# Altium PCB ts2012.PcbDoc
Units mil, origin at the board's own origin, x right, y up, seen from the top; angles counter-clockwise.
Board outline 1935.03 x 1190.03 mil, 2 copper layers (Top Layer, Bottom Layer); 16 components, 15 nets, 62 pads, 7 vias.
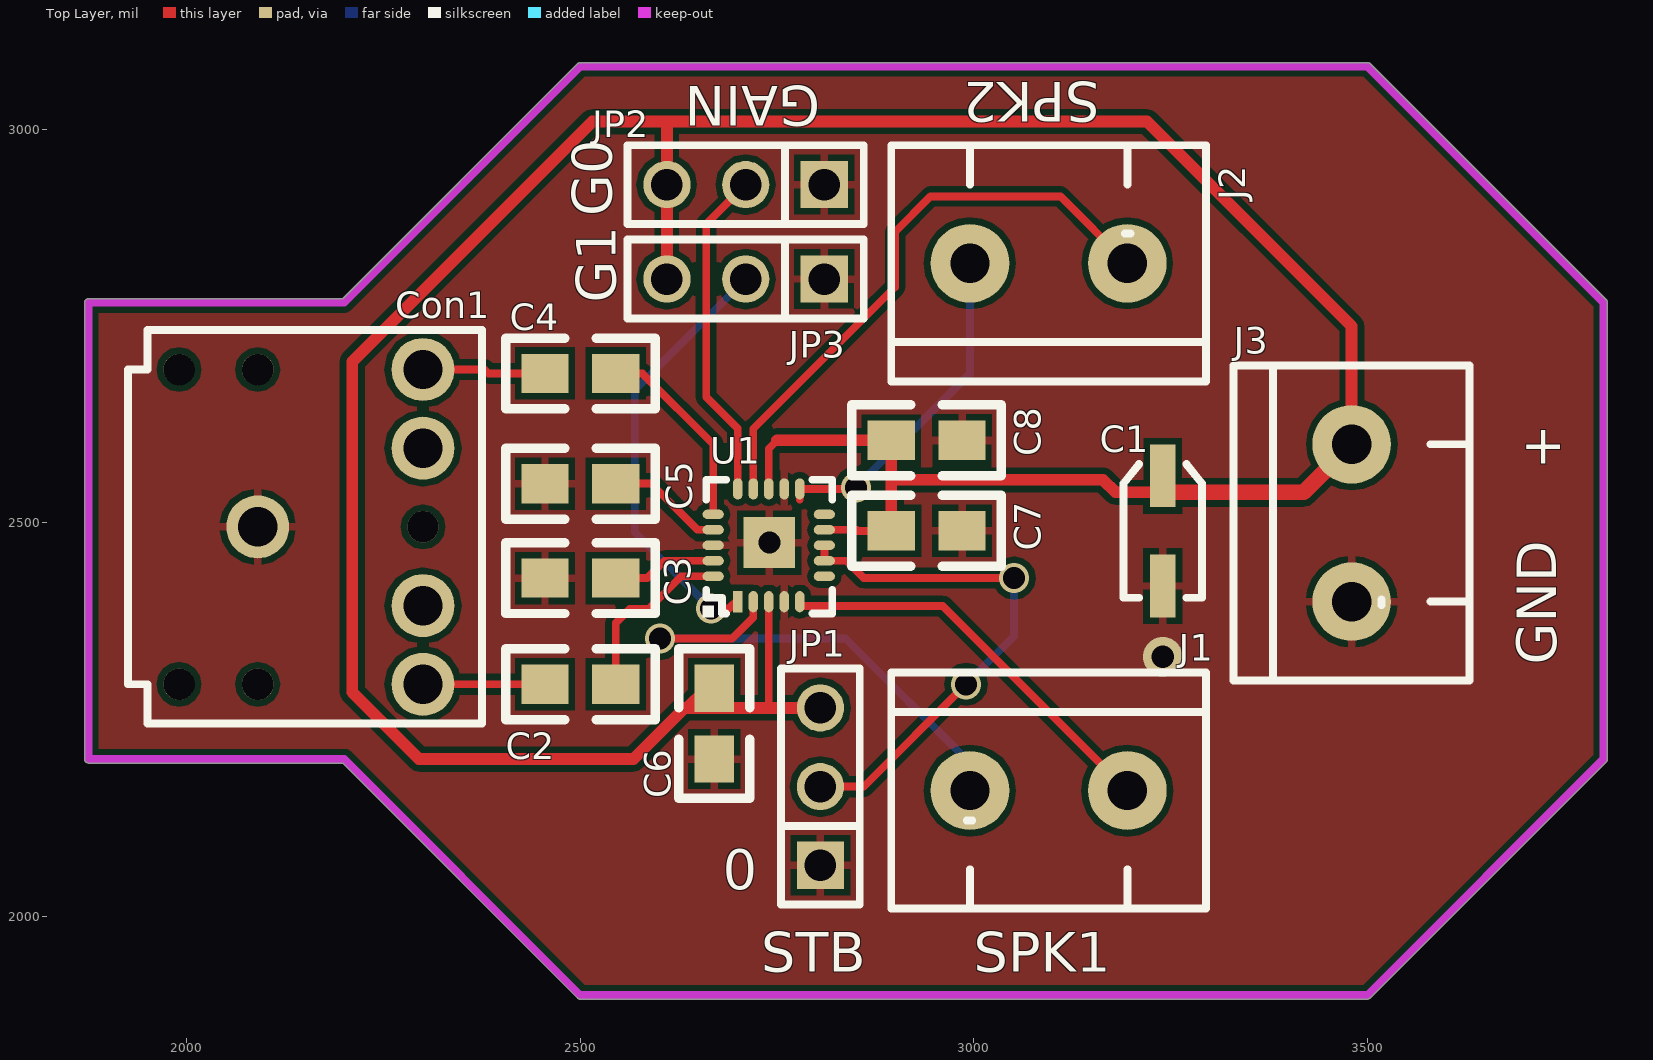
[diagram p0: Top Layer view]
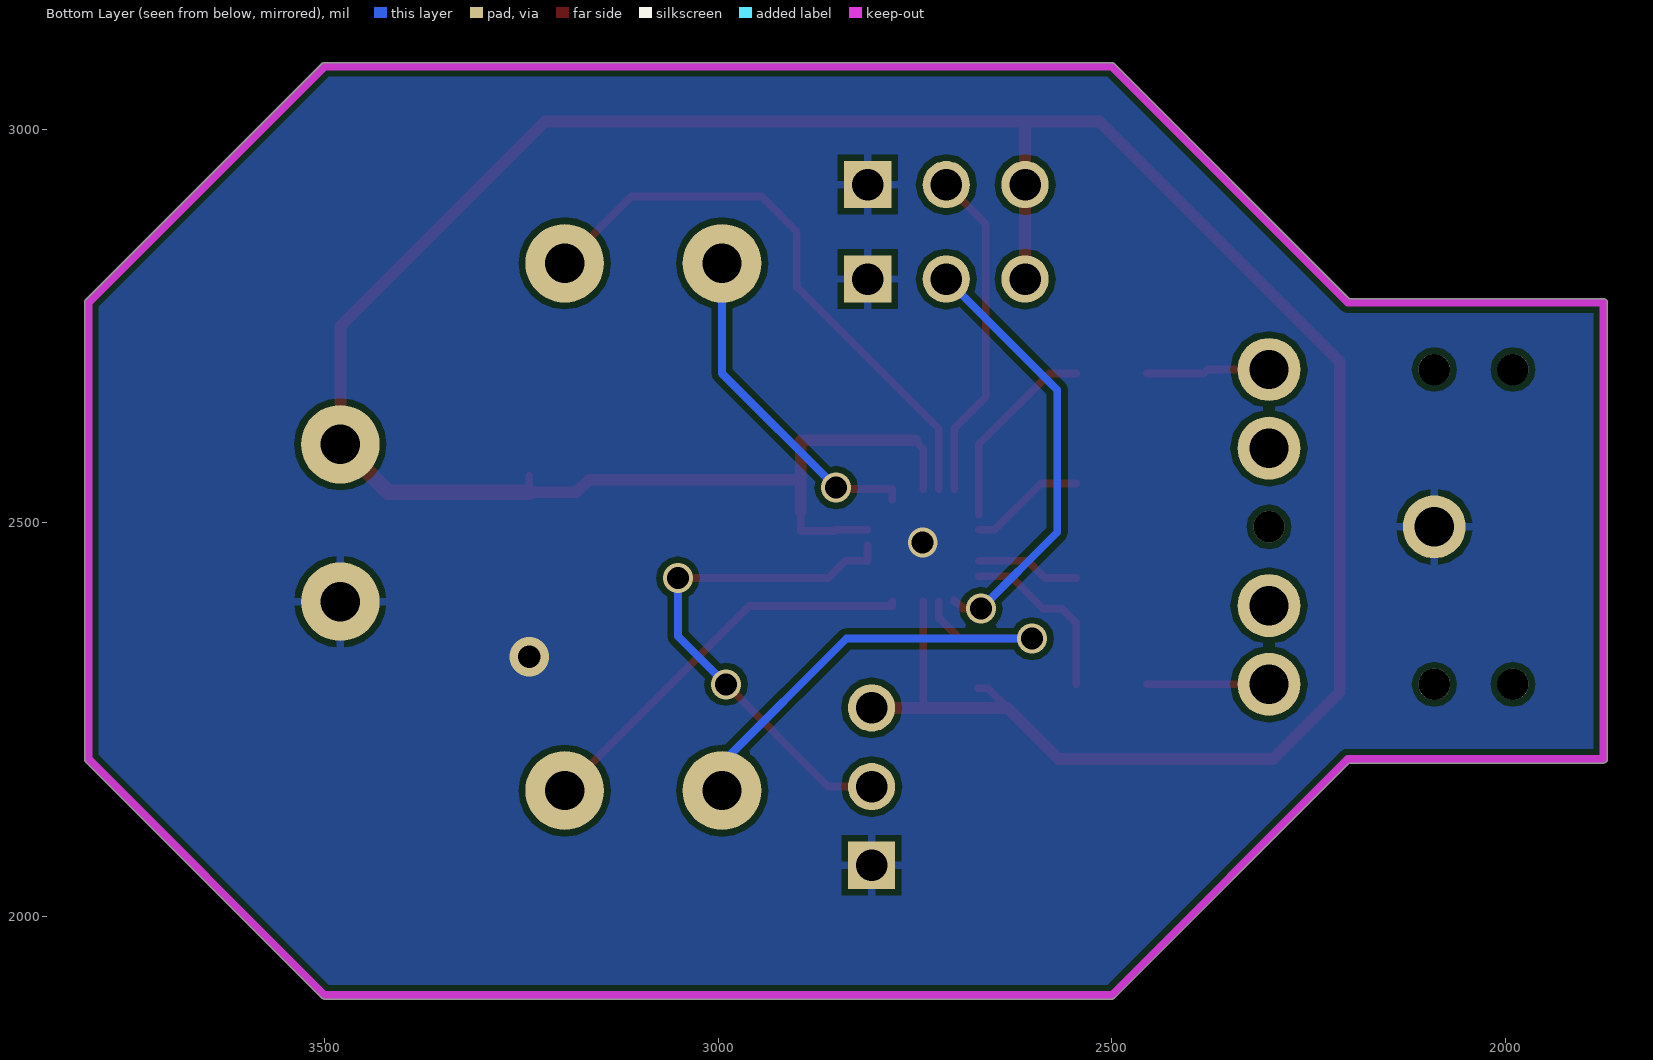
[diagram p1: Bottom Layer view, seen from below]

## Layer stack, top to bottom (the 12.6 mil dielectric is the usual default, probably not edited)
Top Layer: signal copper 1.4
Dielectric: dielectric 12.6, FR-4, Dk 4.8
Bottom Layer: signal copper 1.4

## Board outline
1875,2194.99 2197.92,2194.99 2496.45,1896.45 2496.44,1896.47 ccw(c2500,1900) 2500,1894.98 3500,1894.98 ccw(c3500,1900) 3503.56,1896.47 3503.55,1896.45 3803.55,2196.45 3803.53,2196.44 ccw(c3800,2200) 3805.01,2200 3805.01,2780 ccw(c3800,2780) 3803.53,2783.56 3803.55,2783.55 3503.55,3083.55 3503.56,3083.53 ccw(c3500,3080) 3500,3085.01 2500,3085.01 ccw(c2500,3080) 2496.44,3083.53 2496.45,3083.55 2197.92,2785.01 1875,2785.01 ccw(c1875,2780) 1869.98,2780 1869.98,2200 ccw(c1875,2200)

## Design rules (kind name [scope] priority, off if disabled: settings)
Clearance [All] p1: gap=8
PolygonConnect [All] p1: connectstyle=Relief reliefconductorwidth=10 reliefentries=4 polygonreliefangle="90 Angle"
RoutingVias [All] p1: holewidth=28 width=50 viastyle="Through Hole" minholewidth=28 minwidth=50 maxholewidth=28 maxwidth=50
SilkscreenOverComponentPads [All] p1: minsilkscreentomaskgap=10
SolderMaskExpansion [All] p1: expansion=4
Width [All] p1: maxlimit=10 minlimit=10 preferedwidth=10
27 further rules are at their usual default settings.

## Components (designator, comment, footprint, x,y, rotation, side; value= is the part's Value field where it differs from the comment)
C1 "10uF" CE_SMD_W 3240,2560 r270 top
C2 "220nF" 0805 2455,2295 r0 top
C3 "220nF" 0805 2455,2430 r0 top
C4 "220nF" 0805 2455,2690 r0 top
C5 "220nF" 0805 2455,2550 r0 top
C6 "1uF" 0805 2670,2290 r270 top
C7 "1uF" 0805 2895,2490 r0 top
C8 "1uF" 0805 2895,2605 r0 top
Con1 "PHONEJACK STEREO" MINIJACK_STEREO 2300,2695 r270 top
J1 "CON2" ARK2 2995,2160 r270 top
J2 "CON2" ARK2 3195,2830 r90 top
J3 "CON2" ARK2 3480,2400 r0 top
JP1 "JP" sip-3 2805,2065 r90 top
JP2 "G0" sip-3 2810,2930 r180 top
JP3 "G1" sip-3 2810,2810 r180 top
U1 "TS2012IQT" QFN20_4X4 2700,2400 r90 top

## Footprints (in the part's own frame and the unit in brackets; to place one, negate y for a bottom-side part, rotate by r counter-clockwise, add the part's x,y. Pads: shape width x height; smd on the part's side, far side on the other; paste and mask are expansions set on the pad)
0805 [mil]
  rect 60x50 smd: 1(0,0) 2(90,0)
  silkscreen extent -50,-45 140,45
ARK2 [mil]
  round 100 hole 50: 1(0,0) 2(0,200)
  silkscreen extent -150,-100 150,300
CE_SMD_W [mil]
  rect 80x33 smd: 1(0,0) 2(140,0)
  silkscreen extent -15,-50 155,50
MINIJACK_STEREO [mil]
  round 40 hole 40: 0(0,-210) 0(0,-310) 0(200,0) 0(400,-310) 0(400,-210)
  round 80 hole 50: 1(0,0) 2(100,0) 3(300,0) 4(400,0) 5(200,-210)
  silkscreen extent -50,-375 450,75
QFN20_4X4 [mil]
  rect 27x12 smd: 1(0,0)
  oval 27x12 smd: 2(0,-19.69) 3(0,-39.37) 4(0,-59.06) 5(0,-78.74) 11(143.26,-78.74) 12(143.26,-59.06) 13(143.26,-39.37) 14(143.26,-19.69) 15(143.26,0)
  oval 12x27 smd: 6(32.26,-110) 7(51.95,-110) 8(71.63,-110) 9(91.32,-110) 10(111,-110) 16(111,31.26) 17(91.32,31.26) 18(71.63,31.26) 19(51.95,31.26) 20(32.26,31.26)
  rect 65x65 smd: EPAD(75,-40)
  Top Layer lines w10: 0,0 2.26,0
  silkscreen extent -20,-120 155,45
sip-3 [mil]
  rect 60x60 hole 40: 1(0,0)
  round 60 hole 40: 2(100,0) 3(200,0)
  silkscreen extent -50,-50 250,50

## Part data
C1: library part CP, "Capacitor"
C2 C3 C4 C5 C6 C7 C8: library part Cap, "Capacitor"
J1 J2 J3: "Connector"
JP1: "Jumper"
JP2 JP3: library part JP, "Jumper"

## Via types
v1: diameter 38, hole 28, Top Layer to Bottom Layer, 6 vias
v2: diameter 50, hole 28, Top Layer to Bottom Layer, 1 vias

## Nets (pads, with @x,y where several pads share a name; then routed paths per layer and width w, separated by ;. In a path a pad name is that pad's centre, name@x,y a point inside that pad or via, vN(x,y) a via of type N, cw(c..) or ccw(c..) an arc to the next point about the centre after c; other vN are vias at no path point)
GND: C1.2 C3.1 C5.1 C6.2 C7.2 C8.2 Con1.5 J3.1 JP1.1 JP2.1 JP3.1 U1.4 U1.12 U1.18 U1.EPAD
  other v1: 2740,2475
  other v2: 3240,2330
NetC2_1: C2.1 Con1.4 | length 155
  Top Layer w10: Con1.4 C2.1
NetC2_2: C2.2 U1.20 | length 226.3
  Top Layer w10: C2.2 2545,2373 2563,2391 2586.74,2391 2628,2432.26 U1.20
NetC3_2: C3.2 U1.19 | length 132.8
  Top Layer w10: C3.2 2585,2430 2606.95,2451.95 U1.19
NetC4_1: C4.1 Con1.1 | length 157.1
  Top Layer w10: Con1.1 2378,2695 2383,2690 C4.1
NetC4_2: C4.2 U1.16 | length 250
  Top Layer w10: C4.2 2578.74,2690 2668.74,2600 U1.16
NetC5_2: C5.2 U1.17 | length 148
  Top Layer w10: C5.2 2590,2550 2648.68,2491.32 U1.17
NetJ1_1: J1.1 U1.2 | length 644.3
  Top Layer w10: v1(2601,2353) 2692.69,2353 2719.69,2380 U1.2
  Bottom Layer w10: v1(2601,2353) 2837,2353 2995,2195 J1.1
NetJ1_2: J1.2 U1.5 | length 518.9
  Top Layer w10: U1.5 2778.74,2394.5 2960.5,2394.5 J1.2
NetJ2_1: J2.1 U1.14 | length 750.3
  Top Layer w10: U1.14 2719.69,2619.69 2900,2800 2900,2870 2945,2915 3110,2915 J2.1
NetJ2_2: J2.2 U1.11 | length 474.6
  Top Layer w10: U1.11@2778.74,2530 U1.11 v1@2850,2543.26
  Bottom Layer w10: v1(2850,2545) 2995,2690 J2.2 J2.2@3040,2830
NetJP1_2: JP1.2 U1.7 U1.8 | length 668.9
  Top Layer w10: JP1.2 2860,2165 v1(2990,2295) ; U1.8 U1.7 2838.05,2451.95 2860,2430 v1(3051,2430)
  Bottom Layer w10: v1(2990,2295) 3051,2356 v1(3051,2430)
NetJP2_2: JP2.2 U1.15 | length 424
  Top Layer w10: U1.15 2700,2620 2660,2660 2660,2880 JP2.2
NetJP3_2: JP3.2 U1.1 | length 555.9
  Top Layer w10: v1(2666,2391.22) 2688.96,2391.22 U1.1@2700,2402.26
  Bottom Layer w10: v1(2666,2391.22) 2569,2488.22 2569,2669 JP3.2
VCC: C1.1 C6.1 C7.1 C8.1 J3.2 JP1.3 JP2.3 JP3.3 U1.3 U1.9 U1.13 | length 4163.8
  Top Layer w10: 2632.35,2265 2657.35,2290 C6.1 ; 2739.37,2265 U1.3 ; U1.13 2739.37,2594.37 2750,2605 ; U1.9 2851,2491.32 2852.32,2490 C7.1 C7.1@2895,2514 ; C1.1@3240,2539 C1.1
  Top Layer w15: JP3.3 JP2.3 2610,3010 ; 2750,2605 C8.1 2895,2555 ; JP1.3 2739.37,2265 2632.35,2265 2567.35,2200 2545,2200 2295,2200 2210,2285 2210,2705 2515,3010 2610,3010 ; C7.1@2895,2514 2895,2555 ; C1.1@3240,2539 3180,2539 3164,2555 2895,2555 ; J3.2 3480,2750 3220,3010 2610,3010
  Top Layer w20: C1.1@3240,2539 3419,2539 J3.2
pads on no net: Con1.0 Con1.2 Con1.3 U1.6 U1.10

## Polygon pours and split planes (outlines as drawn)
GND on Top Layer "Top Layer-No Net" (solid, remove dead copper, pour order 2): 1865,2790 1865,2190 2190,2190 2200,2180 2490,1890 2605,1890 3505,1890 3510,1895 3810,2195 3810,2200 3810,2800 3520,3090 3410,3090 2495,3090 2490,3085 2195,2790
GND on Bottom Layer "Top Layer-No Net" (solid, remove dead copper, pour order 4): 1865,2185 2195,2185 2205,2175 2490,1890 2565,1890 3505,1890 3540,1925 3810,2195 3810,2220 3810,2790 3510,3090 3505,3090 2490,3090 2460,3060 2200,2800 2200,2795 1880,2795 1860,2775 1875,2760 1875,2190

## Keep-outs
Keep-Out Layer:
  lines w10: 1875,2485 1875,2780 2200,2780 2500,3080 3500,3080 3800,2780 3800,2280 ; 1875,2495 1875,2200 2200,2200 2500,1900 3500,1900 3800,2200 3800,2700

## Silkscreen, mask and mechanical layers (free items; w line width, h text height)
Top Overlay:
  text "SPK2" at 3160,3060 h50 r180
  text "GAIN" at 2805,3055 h50 r180
  text "G0" at 2540,2890 h50 r90
  text "G1" at 2545,2780 h50 r90
  text "+" at 3695,2575 h50
  text "GND" at 3740,2320 h50 r90
  text "0" at 2725,2085 h50 r180
  text "STB" at 2730,1930 h50
  text "SPK1" at 3000,1930 h50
